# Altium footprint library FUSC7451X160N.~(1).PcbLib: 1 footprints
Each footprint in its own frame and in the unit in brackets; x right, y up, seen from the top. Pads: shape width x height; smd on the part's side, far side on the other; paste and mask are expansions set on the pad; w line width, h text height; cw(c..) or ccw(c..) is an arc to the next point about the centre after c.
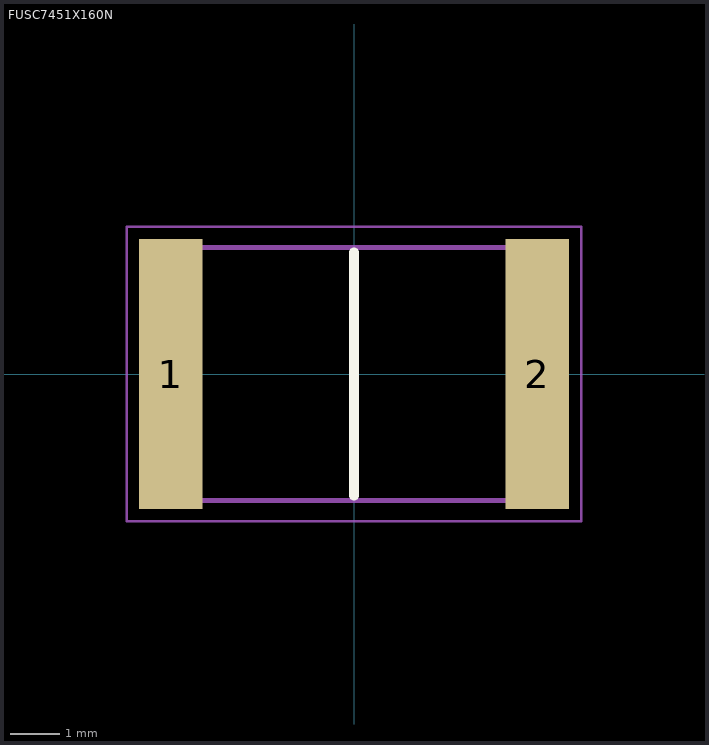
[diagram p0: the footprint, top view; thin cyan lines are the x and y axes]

## FUSC7451X160N [mm]
pads (2):
  rect 1.28x5.45 smd: 1(-3.705,0) 2(3.705,0)
Top Overlay:
  lines w0.2: 0,-2.46 0,2.46
Mechanical 15:
  lines w0.1: -3.678,-2.56 3.678,-2.56 3.678,2.56 -3.678,2.56 -3.678,-2.56
Mechanical 20:
  lines w0.05: -4.595,-2.975 4.595,-2.975 4.595,2.975 -4.595,2.975 -4.595,-2.975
